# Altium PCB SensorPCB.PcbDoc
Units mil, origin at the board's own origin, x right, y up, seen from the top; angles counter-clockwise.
Board outline 430 x 380 mil, 2 copper layers (Top Layer, Bottom Layer); 10 components, 9 nets, 41 pads, 16 vias.
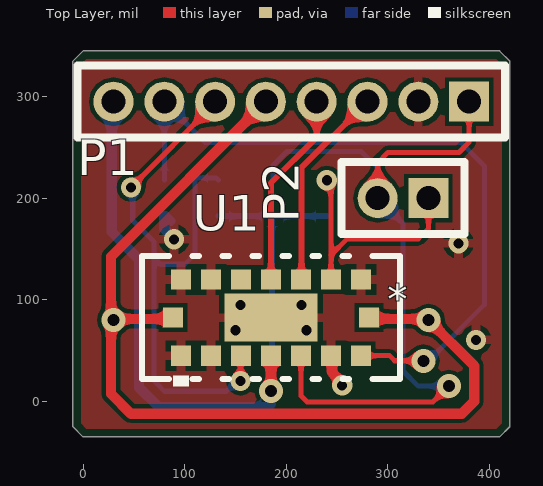
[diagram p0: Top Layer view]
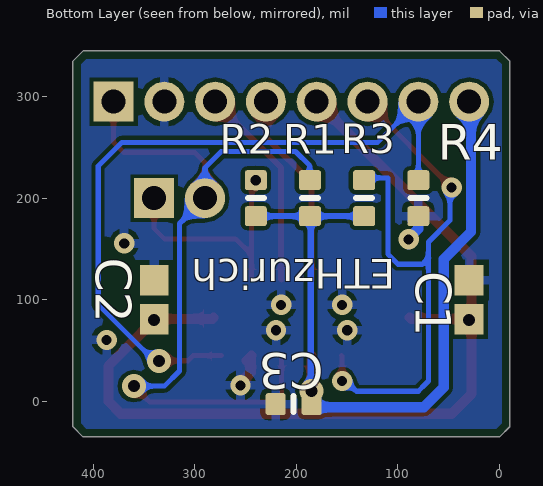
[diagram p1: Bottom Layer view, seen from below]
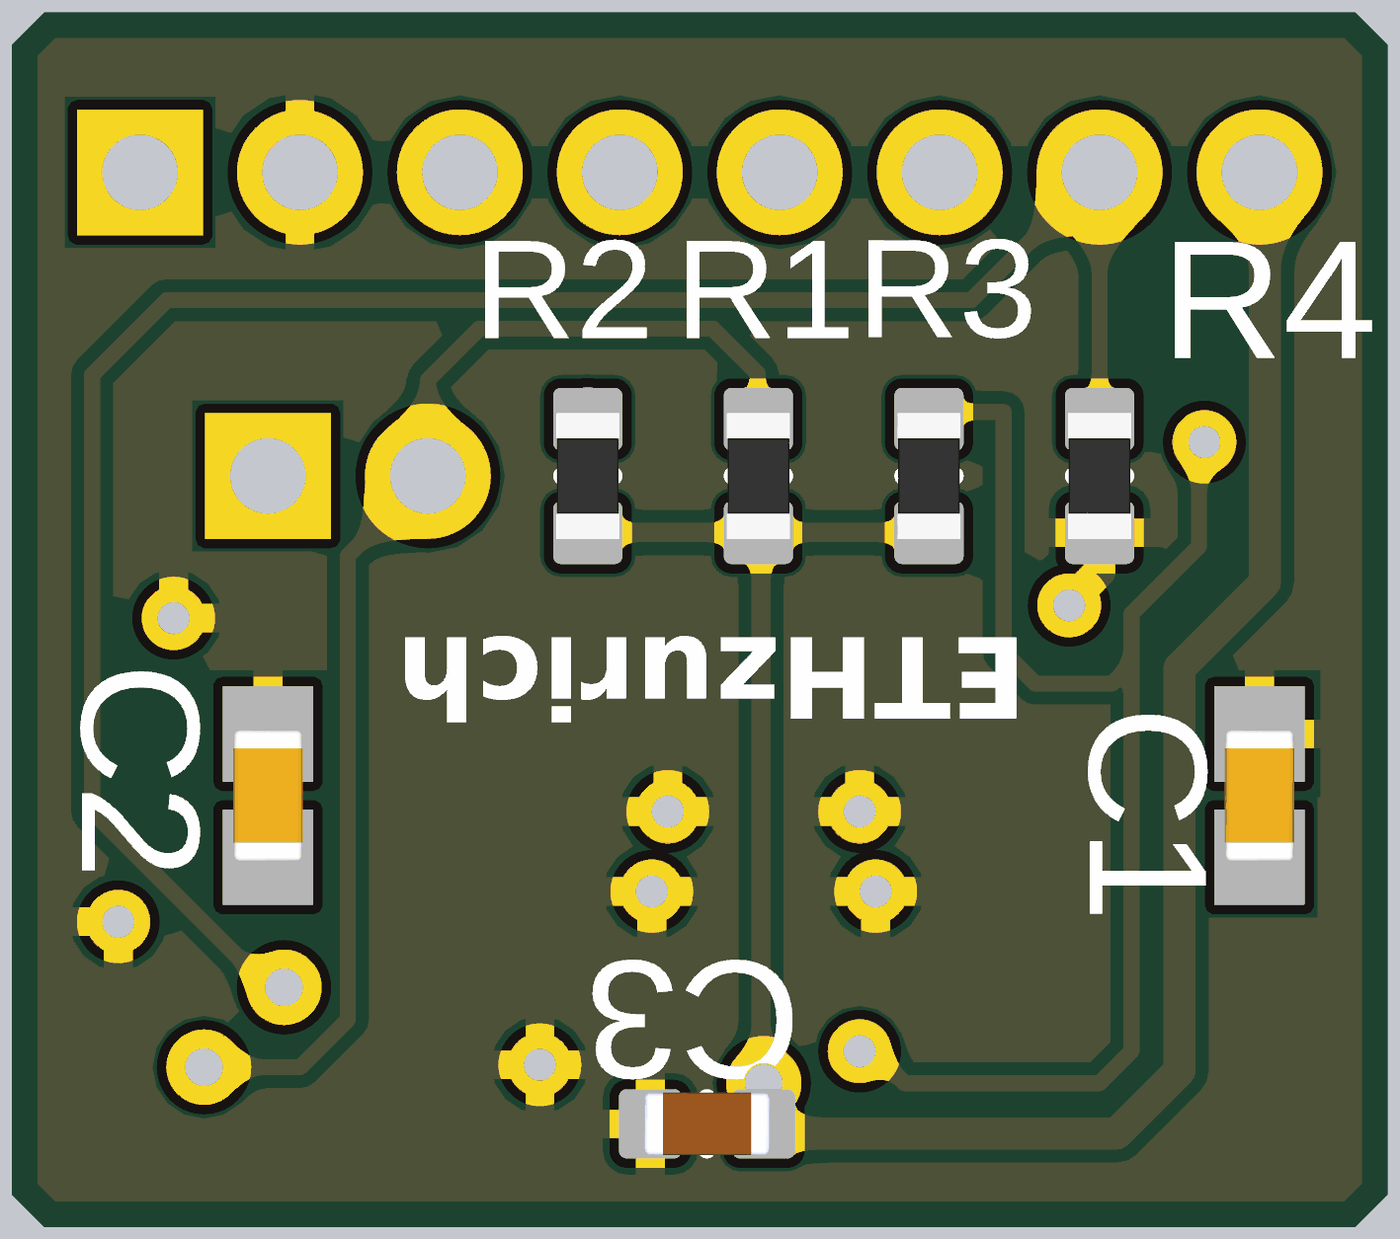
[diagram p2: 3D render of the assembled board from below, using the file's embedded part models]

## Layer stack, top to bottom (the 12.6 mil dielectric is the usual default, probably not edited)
Top Solder: solder mask 0.4, Solder Resist, Dk 3.5
Top Layer: signal copper 1.4
Dielectric 1: dielectric 12.6, FR-4, Dk 4.8
Bottom Layer: signal copper 1.4
Bottom Solder: solder mask 0.4, Solder Resist, Dk 3.5

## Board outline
-10,-25 -10,335 0,345 410,345 420,335 420,-25 410,-35 0,-35

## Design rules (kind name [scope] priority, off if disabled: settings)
AcuteAngle [All] p1: minimum=6.00000000000000E+0001 checktracksonly=TRUE
BoardOutlineClearance switch [InComponent('SW1')] p1: gap=7.87 ignorepadtopadclearanceinfootprint=FALSE except(23.62: Track-OutlineEdge Track-CavityEdge Track-CutoutEdge Track-SplitBarrior Track-SplitContinuation)
BoardOutlineClearance [All] p2: gap=7.87 ignorepadtopadclearanceinfootprint=FALSE
Clearance Clearance_bga [TouchesRoom('VSOCBKP_BGA') or TouchesRoom('VCLUST_BGA')                  or TouchesRoom('uC_BGA')] p1: gap=2.95 ignorepadtopadclearanceinfootprint=FALSE except(0: Arc-Hole Track-Hole SMDPad-Hole THPad-Hole Via-Hole Fill-Hole Poly-Hole Region-Hole Text-Hole)
Clearance Clearance_pulp [All] p2: gap=3.94 ignorepadtopadclearanceinfootprint=FALSE except(0: Arc-Hole Track-Hole SMDPad-Hole THPad-Hole Via-Hole Fill-Hole Poly-Hole Region-Hole Text-Hole)
Clearance [All] p3: gap=4.92 ignorepadtopadclearanceinfootprint=FALSE except(0: Arc-Hole Track-Hole SMDPad-Hole THPad-Hole Via-Hole Fill-Hole Poly-Hole Region-Hole Text-Hole)
ComponentClearance ComponentClearance_moreweirdtphole [InComponent('TP27') vs InComponent('U2')] p1: gap=0 collisioncheckmode=3 verticalgap=0 showdistances=FALSE
ComponentClearance ComponentClearance_weird_tp_holes [InComponent('TP25') vs InComponent('TP26')] p2: gap=0 collisioncheckmode=3 verticalgap=0 showdistances=FALSE
ComponentClearance ComponentClearance_TPunderlatch [InComponent('U2') vs InComponent('TP23') or InComponent('JP21') or InComponent('JP27') or InComponent('JP24') or InComponent('JP25') or InComponent('JP26')] p3: gap=0 collisioncheckmode=3 verticalgap=0 showdistances=FALSE
ComponentClearance ComponentClearance_NetTie [InComponentClass('NetTie')] p4: gap=0 collisioncheckmode=3 verticalgap=0 showdistances=TRUE
ComponentClearance ComponentClearance_Hole [InComponentClass('Holes, Screws etc.')] p5: gap=0 collisioncheckmode=3 verticalgap=0 showdistances=TRUE
ComponentClearance [All] p6: gap=9.84 collisioncheckmode=3 verticalgap=9.84 showdistances=TRUE
DiffPairsRouting [All] p1: maxlimit=15 minlimit=4.92 mostfreqgap=4.92 toplayer_minwidth=4.92 toplayer_maxwidth=15 toplayer_prefwidth=11.81 bottomlayer_minwidth=4.92 bottomlayer_maxwidth=15 bottomlayer_prefwidth=11.81 maxuncoupledlength=500
FabricationTestpoint [All] p1: side=3 testpointundercomponent=TRUE minsize=19.68 maxsize=100 preferedsize=60 minholesize=0 maxholesize=40 preferedholesize=32 testpointgrid=1 allowsidetop=TRUE allowsidebottom=TRUE usegrid=TRUE gridtolerance=0.01
FanoutControl Fanout_BGA_1 [InComponent('U1')] p1: bgadir=Out bgaviamode=Centered fanoutstyle=BGA fanoutdirection=Alternating viagrid=1 // Fanout_BGA (Default Rule)
FanoutControl Fanout_BGA [IsBGA] p2: bgadir=Out bgaviamode=Centered fanoutstyle=Auto fanoutdirection=Alternating viagrid=1 // Fanout_BGA (Default Rule)
FanoutControl Fanout_LCC [IsLCC] p3: bgadir=Out bgaviamode=Centered fanoutstyle=Auto fanoutdirection=Alternating viagrid=1 // Fanout_LCC (Default Rule)
FanoutControl Fanout_SOIC [IsSOIC] p4: bgadir=Out bgaviamode=Centered fanoutstyle=Auto fanoutdirection=Alternating viagrid=1 // Fanout_SOIC (Default Rule)
FanoutControl Fanout_Small [(CompPinCount < 5)] p5: bgadir=Out bgaviamode=Centered fanoutstyle=Auto fanoutdirection=OutThenIn viagrid=1 // Fanout_Small (Default Rule)
FanoutControl Fanout_Default [All] p6: bgadir=Out bgaviamode=Centered fanoutstyle=Auto fanoutdirection=Alternating viagrid=1 // Fanout_Default (Default Rule)
Height [All] p1: minheight=0 maxheight=1968.5 prefheight=500
HoleSize [All] p1: absolutevalues=TRUE maxlimit=196.85 minlimit=7.87 maxpercent=80.000 minpercent=20.000
HoleToHoleClearance [All] p1: gap=9.84 allowstackedmicrovias=FALSE
Length "InNet('CLK_0') Or InNet('CLK_1')" [InNet('CLK_0') Or InNet('CLK_1')] p1: maxlimit=1447.75 minlimit=0
MinimumAnnularRing MinimumAnnularRing_Vias_bga [Isvia and TouchesRoom('GAP')] p1: minimumring=3.94
MinimumAnnularRing MinimumAnnularRing_Vias [Isvia] p2: minimumring=4.88
MinimumAnnularRing [All] p3: minimumring=5.91
MinimumSolderMaskSliver MinimumSolderMaskSliver_1 [InComponent('U2') and IsPad and InNet('GND')] p1: minsoldermaskwidth=0
MinimumSolderMaskSliver [All] p2: minsoldermaskwidth=3.93
PlaneClearance "Mounting Holes" [InPadClass('ExtendedClearance')] p1: clearance=82.68
PlaneClearance [All] p2: clearance=7.87
PlaneConnect [All] p1: planeconnectstyle=Direct reliefexpansion=20 reliefentries=4 reliefconductorwidth=10 reliefairgap=10
PolygonConnect [All] p1: connectstyle=Relief reliefconductorwidth=9 reliefentries=4 polygonreliefangle="90 Angle" airgapwidth=4.92
RoutingVias RoutingVias_BGA [TouchesRoom('GAP')] p1: holewidth=7.87 width=15.75 viastyle="Through Hole" minholewidth=7.87 minwidth=15.75 maxholewidth=11.81 maxwidth=23.62 viatemplateguid#1={47C5AC95-9C33-4135-A81B-A9012375E807} viatemplatename#1=v40h15x30m0mx0
RoutingVias [All] p2: holewidth=7.87 width=17.72 viastyle="Through Hole" minholewidth=7.87 minwidth=17.72 maxholewidth=11.81 maxwidth=23.62
ShortCircuit ShortCircuit_variant_footprint [IsPad and not InAnyNet vs IsPad and not InAnyNet] p1: allowed=TRUE
ShortCircuit [All] p2: allowed=FALSE
SilkToSilkClearance "SilkText Exception" [OnSilkscreen  And (IsText And Not IsDesignator) vs OnSilkscreen  And ((IsText And Not IsDesignator) or IsTrack)] p1: silktosilkclearance=0
SilkToSilkClearance [All] p2: silktosilkclearance=3.94
SilkToSolderMaskClearance [IsPad] p1: minsilkscreentomaskgap=3.94 clearancetoexposedcopper=TRUE
SolderMaskExpansion [All] p1: expansion=2.95 istentingtop=FALSE
Width Width_bga [All] p1: maxlimit=23.62 minlimit=3.94 preferedwidth=4.92 minimp=50.000000 maximp=50.000000 favimp=50.000000
Width Width_PWR [InNetClass('POWER')] p2: maxlimit=23.62 minlimit=5.91 preferedwidth=7.87 minimp=50.000000 maximp=50.000000 favimp=50.000000
Width [All] p3: maxlimit=23.62 minlimit=5.91 preferedwidth=5.91 minimp=50.000000 maximp=50.000000 favimp=50.000000
13 further rules are at their usual default settings.

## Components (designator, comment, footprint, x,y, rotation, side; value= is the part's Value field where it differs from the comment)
C1 "Capacitor 1 uF +/- 10% 6.3 V 1005" CAPC1005X55X25ML5T10 30,100 r270 bottom value=4.7µF
C2 "Capacitor 1 uF +/- 10% 6.3 V 1005" CAPC1005X55X25ML5T10 340,100 r270 bottom value=4.7µF
C3 "Capacitor 100nF +/-20% 25V 0402" CAPC0402(1005)60_L 202.72,-2.72 r180 bottom value=100nF
P1 "Sensor" MHDR1X8 380,295 r180 top locked
P2 "Extra IOs" MHDR1X2 340,200 r180 top locked
R1 "Resistor 47K5 +/-1 % 0402 63 mW" RESC0402(1005)_L 186.67,200 r270 bottom value=47k
R2 "Resistor 47K5 +/-1 % 0402 63 mW" RESC0402(1005)_L 240,200 r270 bottom value=47k
R3 "Resistor 47K5 +/-1 % 0402 63 mW" RESC0402(1005)_L 133.33,200 r270 bottom value=47k
R4 "Resistor 47K5 +/-1 % 0402 63 mW" RESC0402(1005)_L 80,200 r90 bottom value=47k
U1 "VL53L5 Forward" ARRAY_53L5_STM 185,82.5 r180 top locked

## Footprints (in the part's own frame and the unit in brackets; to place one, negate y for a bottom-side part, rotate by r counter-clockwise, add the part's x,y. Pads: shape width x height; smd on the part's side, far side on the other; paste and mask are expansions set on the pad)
ARRAY_53L5_STM [mil]
  rect 20x20 smd paste+0 mask+0: A1(-88.58,37.5) A2(-59.06,37.5) A3(-29.53,37.5) A4(0,37.5) A5(29.53,37.5) A6(59.06,37.5) A7(88.58,37.5) B1(-96.5,0) B7(96.5,0) C1(-88.58,-37.5) C2(-59.06,-37.5) C3(-29.53,-37.5) C4(0,-37.5) C5(29.53,-37.5) C6(59.06,-37.5) C7(88.58,-37.5)
  rect 92x47 smd paste-45.5 mask+0: B4(0,0)
  silkscreen extent -127,-61 127,68, body extent -125,-60 125,60, height 10
CAPC0402(1005)60_L [mm] "Chip Capacitor, Body 1.0x0.5mm, Height 0.6mm, IPC High Density"
  rrect25% 0.5x0.55 smd: 1(-0.45,0) 2(0.45,0)
  silkscreen extent 0,-0.2 0,0.2, body extent -0.5,-0.25 0.5,0.25, height 0.6
CAPC1005X55X25ML5T10 [mm] "Chip Capacitor, 2-Leads, Body 1.05x0.55mm, IPC Low Density"
  rect 0.76x0.72 smd: 1(-0.49,0) 2(0.49,0)
  body extent -0.53,-0.28 0.53,0.28, height 0.55
MHDR1X2 [mm] "Connector; Header; 2 Position"
  rect 1x1 hole 0.6: 1(0,0)
  round 1 hole 0.6: 2(1.27,0)
  silkscreen extent -0.9,-0.9 2.17,0.9
MHDR1X8 [mm] "Connector; Header; 8 Position"
  rect 1x1 hole 0.6: 1(0,0)
  round 1 hole 0.6: 2(1.27,0) 3(2.54,0) 4(3.81,0) 5(5.08,0) 6(6.35,0) 7(7.62,0) 8(8.89,0)
  silkscreen extent -0.9,-0.9 9.79,0.9
RESC0402(1005)_L [mm] "Chip Resistor, Body 1.0x0.5mm, IPC High Density"
  rrect25% 0.5x0.55 smd: 1(-0.45,0) 2(0.45,0)
  silkscreen extent 0,-0.2 0,0.2, body extent -0.5,-0.25 0.5,0.25, height 0.3

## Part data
C1 C2: library part CMP-001-00009-6, "Chip Capacitor, 1 uF, +/- 10%, 6.3 V, 1005 (0402 Metric)", Capacitor Type=Ceramic, Case/Package=0402, Max Operating Temperature=85°C, Min Operating Temperature=-55°C, Tolerance=10%, Voltage Rating=6.3V
C3: library part CMP-001-00065-4, "Chip Capacitor, 100nF +/-20%, 25V, 0402, Thickness 0.6 mm", Case/Package=0402, Max Operating Temperature=85°C, Min Operating Temperature=-55°C, Tolerance=10%, Voltage Rating=25V
P1: library part MHDR1X8, "Header, 8-Pin"
P2: library part MHDR1X2, "Header, 2-Pin"
R1 R2 R3 R4: library part CMP-009-00137-3, "Chip Resistor, 47,5 kOhms, +/-1 %, 63 mW, -55 to 155 degC, 0402", Case/Package=0402, Max Operating Temperature=155°C, Min Operating Temperature=-55°C, Power=63mW, Tolerance=1%
U1: library part VL53L5, "No Description Available"

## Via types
v1: diameter 20, hole 10, Top Layer to Bottom Layer, 11 vias
v2: diameter 23.62, hole 11.81, Top Layer to Bottom Layer, 5 vias

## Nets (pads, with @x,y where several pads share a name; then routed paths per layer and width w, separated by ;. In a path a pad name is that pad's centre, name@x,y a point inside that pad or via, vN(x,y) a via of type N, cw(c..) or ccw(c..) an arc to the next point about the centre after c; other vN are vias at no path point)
AVDD: C1.2 C2.2 P1.5 U1.B1 U1.B7 | length 941.6
  Top Layer w10: U1.B7 87.25,81.25 31.25,81.25 v2(30,80) ; P1.5 27.5,142.5 27.5,82.5 v2(30,80) ; U1.B1 282.75,81.25 338.75,81.25 v2(340,80) 385,35 385,0 372.87,-12.13 47.13,-12.13 27.5,7.5 27.5,77.5 v2(30,80)
  Bottom Layer w10: C2.2 C2.2@340.35,80.35
GND: C1.1 C2.1 C3.1 P1.2 R4.1 U1.A2 U1.A6 U1.A7 U1.B4 U1.C1 U1.C6 U1.C7 | length 76.8
  Top Layer w10: U1.A2 U1.A2@245,44.06 ; U1.A2@249.06,40 U1.A2@245,44.06 ; v1(255,15.75) 255,18.45 245,28.45 U1.A2@245,44.06
  Bottom Layer w10: R4.1@85.83,177.44 80.98,182.28 R4.1 80,170 v1@89.5,160.5 ; v1@89.5,154.5 v1@89.5,155.5 ; v1(89.5,159.5) v1@89.5,160.5 ; v1@89.5,162.21 v1@89.5,160.5
  other v1: 386.8,60.5 150,70 220,70 155,95 215,95 369.5,155.5
GPIO1(INT): P1.1 P2.2 R1.1 U1.A3 | length 758.9
  Top Layer w5: U1.A3 214.53,5.47 220.69,-0.69 344.31,-0.69 v2(360,15) ; P2.2 290,235 300,245 370,245 380,255 P1.1
  Bottom Layer w5: R1.1 186.94,217.99 186.94,232.13 200.87,246.06 273.94,246.06 290,230 P2.2 315,175 315,30 330,15 v2(360,15)
GPIO2(RSVD6): P2.1 R2.1 U1.C2 | length 236.7
  Top Layer w5: v1(240,217.72) 241.13,217.72 244.06,214.79 244.06,144.06 ; U1.C2 244.06,144.06 ; P2.1 340,170 330,160 260,160 244.06,144.06
I2C_RST: P1.7 R4.2 U1.A1 | length 701.5
  Top Layer w5: U1.A1 301.79,45 306.79,40 v2(335,40)
  Bottom Layer w5: R4.2 P1.7 120,255 371.7,255 395,231.7 395,95 340,40 v2(335,40)
IOVDD: C3.2 P1.8 R1.2 R2.2 R3.2 U1.A4 | length 759.6
  Top Layer w10: v2(185,10) U1.A4
  Bottom Layer w6: R3.2 R1.2 ; v2(185,10) 185.83,10.83 185.83,181.45 R1.2 ; R2.2 R1.2
  Bottom Layer w10: P1.8 28.29,293.29 28.29,166.71 55,140 55,13.94 74.69,-5.75 181.97,-5.75 C3.2 v2(185,10)
LPn: P1.6 R3.1 U1.A5 | length 591.3
  Top Layer w5: v1(47.23,210.58) 130,293.35 P1.6 ; v1(155,20) 155,44.53 U1.A5
  Bottom Layer w5: v1(47.23,210.58) 48.94,208.87 48.94,177.98 70,156.91 70,141.17 ; R3.1 131.05,220 110.01,220 110,145 100,135 76.17,135 70,141.17 ; 70,141.17 70,20.06 72.93,17.13 80.06,10 140.94,10 v1@148.07,17.13 ; v1@148.07,17.13 150.94,20 v1(155,20) 152.13,17.13 v1@148.07,17.13
SCL: P1.4 U1.C4 | length 193.6
  Top Layer w6: U1.C4 185,215 230,260 P1.4
SDA: P1.3 U1.C3 | length 202.1
  Top Layer w6: U1.C3 215,120.47 215,230 P1.3
pads on no net: U1.C5

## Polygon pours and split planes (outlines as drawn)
GND on Bottom Layer "GND_L02_P001" (solid, pour order 1): 410,345 420,335 420,-25 410,-35 0,-35 -10,-25 -10,335 0,345
GND on Top Layer "GND_L01_P002" (solid, pour order 2): 0,345 -10,335 -10,-25 0,-35 410,-35 420,-25 420,335 410,345

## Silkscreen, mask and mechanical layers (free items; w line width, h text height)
Bottom Overlay:
  text "ETHzurich" at 102.7,149.51 h50 r180
Mechanical 1:
  the board outline again, w1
